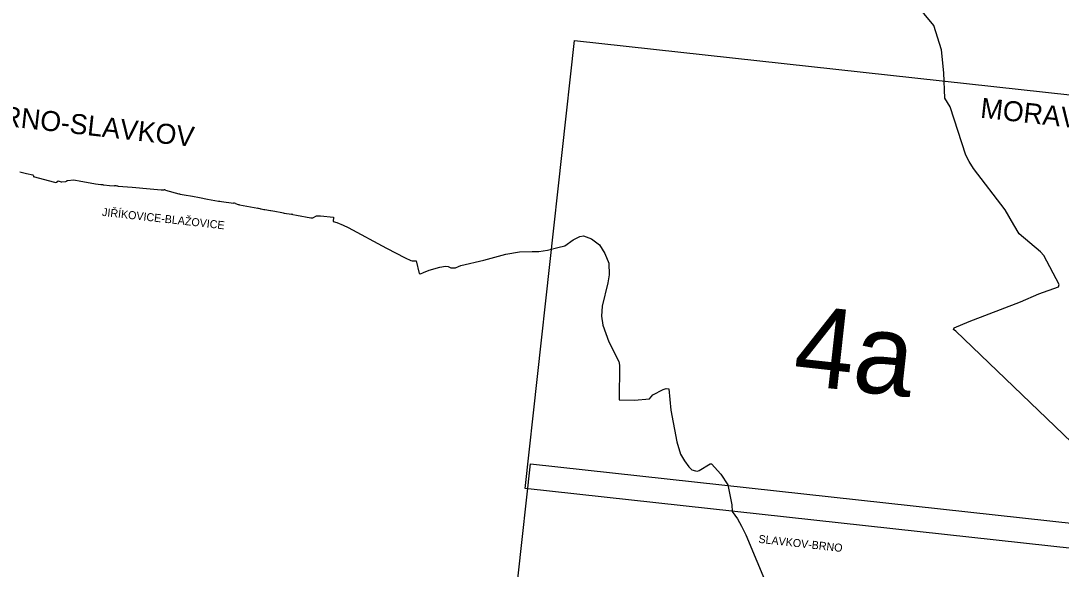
# Model space of a CAD drawing. Extents: x -678204 to -526855, y -1228851 to -1110393.
# Drawn here: x -587930 to -580130, y -1168017 to -1163908 of the extents above; entities that cross this region are included whole.
import ezdxf

# ---------------------------------------------------------------- set-up
doc = ezdxf.new("R2010")
doc.units = 0
for name, color, linetype in [('00_n_cyklo popisy detaily', 7, 'Continuous'), ('00_n_cyklo popisy ostatni', 7, 'Continuous'), ('00_n_cyklo provereni vedlejsi', 7, 'Continuous'), ('00_n_cyklo prujezdne rekreacni vedlejsi', 7, 'Continuous'), ('00_n_cyklo realizace rekreacni vedlejsi', 7, 'Continuous'), ('00_n_cyklo studie rekreacni vedlejsi', 7, 'Continuous'), ('00_n_cyklo trasovani rekreacni vedlejsi', 7, 'Continuous'), ('_HELP', 7, 'Continuous')]:
    doc.layers.add(name, color=color, linetype=linetype)

msp = doc.modelspace()

# ---------------------------------------------------------------- linework, layer by layer
at = {"layer": '00_n_cyklo provereni vedlejsi'}
for points in [[(-581001.8, -1164487.7), (-581010.3, -1164297.8), (-581026.2, -1164126.2), (-581083.9, -1163943.9), (-581156.1, -1163856.2), (-581240.3, -1163785.5), (-581281.7, -1163715.5), (-581430.8, -1163359.5), (-581479.7, -1163227.3), (-581607.1, -1162771.8), (-581858.6, -1162250.9), (-582154.7, -1161867.5), (-582292.2, -1161719.3), (-582389.3, -1161653.4), (-582541.6, -1161550.7), (-582550.7, -1161521.1), (-582545.6, -1161437.7), (-582553.9, -1161420.4), (-582652.6, -1161350.3), (-582831.3, -1161299.1)], [(-580285.4, -1165640.1), (-580444.5, -1165505.1), (-580486.1, -1165437.1), (-580549.4, -1165323.8), (-580787.3, -1165013.2), (-580820.8, -1164961.9), (-580844.2, -1164914.3), (-580962, -1164553.5), (-581001.8, -1164487.7)], [(-580919, -1166234.2), (-580938.2, -1166220.3), (-580933.4, -1166209.2), (-580819.5, -1166160.9), (-580434.6, -1166012.5), (-580297.3, -1165953.9), (-580150.3, -1165900.5), (-580144.5, -1165884.8), (-580259.7, -1165667.5), (-580285.4, -1165640.1)], [(-580919, -1166234.2), (-579989.5, -1167124.1), (-579982.8, -1167138.4), (-579949.1, -1167129.4), (-579898.3, -1167123.6), (-579497.8, -1167124.8), (-579364.8, -1167130.1), (-579317.1, -1167128), (-579260, -1167124.2), (-579233, -1167115.8)]]:
    msp.add_lwpolyline(points, dxfattribs=at)
at = {"layer": '00_n_cyklo prujezdne rekreacni vedlejsi'}
msp.add_line((-584995.4, -1165705.5), (-584965.2, -1165705.7), dxfattribs=at)
for points in [[(-585862, -1165364.7), (-585755.4, -1165384.4), (-585740.8, -1165383.1), (-585711.8, -1165369.2), (-585704.5, -1165368.5), (-585682.7, -1165368.5), (-585584.9, -1165380.2)], [(-585584.9, -1165380.2), (-585587.7, -1165410.6), (-585559.6, -1165419.1), (-585511.9, -1165438.5), (-585474.5, -1165455.5), (-585187.9, -1165610.7), (-585047.2, -1165684.9), (-585006, -1165704), (-584995.4, -1165705.5)], [(-584965.2, -1165705.7), (-584944.2, -1165802.4), (-584932, -1165803.7), (-584909.5, -1165793.6), (-584869.2, -1165776.2), (-584787.7, -1165752.9), (-584746.2, -1165746.3), (-584726.5, -1165749.1), (-584705.9, -1165758.1), (-584690.6, -1165759.6), (-584671.3, -1165758.5), (-584647.3, -1165749.4), (-584631.1, -1165741.1), (-584458.6, -1165701.6), (-584293.3, -1165656.8), (-584191.4, -1165637.9), (-584095.9, -1165637.5), (-584045.1, -1165636.5), (-583981.8, -1165626.8), (-583902.5, -1165606.7), (-583850, -1165593.2), (-583787.6, -1165548.3), (-583739.3, -1165523.6), (-583710.5, -1165518.4), (-583650.8, -1165540.6)], [(-583650.8, -1165540.6), (-583591.1, -1165586.9), (-583550.4, -1165650.2), (-583521.6, -1165724.5), (-583519.6, -1165810.9), (-583528.4, -1165872), (-583570.3, -1166045.5), (-583576.5, -1166120.3), (-583565.8, -1166187.4), (-583520.3, -1166312.4), (-583445.3, -1166461.8), (-583441.5, -1166489.3), (-583442.8, -1166747.9), (-583329, -1166750.2), (-583216.5, -1166739.8), (-583192, -1166710.3), (-583114.7, -1166670.3), (-583091.9, -1166663.7), (-583072.3, -1166666.1), (-583056.5, -1166824.3), (-583012.7, -1167062.9), (-582982.8, -1167155), (-582953.5, -1167206), (-582920.5, -1167249.8), (-582898.5, -1167272.6), (-582871.5, -1167280.4), (-582856.7, -1167282.7), (-582845.2, -1167277.6), (-582762.7, -1167227.4), (-582751.7, -1167226.8), (-582682.2, -1167306.2), (-582628.2, -1167384.4), (-582598.9, -1167534.1), (-582597.2, -1167584.1), (-582555.7, -1167639.5), (-582527.8, -1167694.1), (-582524.5, -1167700.9)], [(-582524.5, -1167700.9), (-582495.5, -1167760.7)], [(-582495.5, -1167760.7), (-582329, -1168154.9), (-582260.4, -1168332)]]:
    msp.add_lwpolyline(points, dxfattribs=at)
at = {"layer": '00_n_cyklo realizace rekreacni vedlejsi'}
for p, q in [((-587937.5, -1165038.6), (-587886.8, -1165051.5)), ((-587886.8, -1165051.5), (-587840.2, -1165062.7)), ((-587834.1, -1165070.5), (-587834, -1165076.1)), ((-587307.9, -1165137.6), (-587266, -1165141)), ((-587266, -1165141), (-587227.9, -1165144.1)), ((-587200.2, -1165146.4), (-587095.4, -1165155.4)), ((-587095.4, -1165155.4), (-586960.6, -1165167)), ((-586960.6, -1165167), (-586876.5, -1165174.3)), ((-586867.6, -1165174.5), (-586855.8, -1165174.2)), ((-586843.9, -1165175.7), (-586743.9, -1165204)), ((-586735.5, -1165205.9), (-586704.1, -1165211.2)), ((-586704.1, -1165211.2), (-586643, -1165222.7)), ((-586643, -1165222.7), (-586589.9, -1165232.6)), ((-586589.9, -1165232.6), (-586530.7, -1165243.2)), ((-586530.7, -1165243.2), (-586447.3, -1165258.2)), ((-586425.7, -1165261.7), (-586334.6, -1165274)), ((-586320.1, -1165277.4), (-586301.1, -1165283.7)), ((-586290.3, -1165286.5), (-586153.1, -1165311.8)), ((-586149.8, -1165312.4), (-586137.1, -1165315)), ((-586128.9, -1165316.5), (-586106.7, -1165320.8)), ((-586099.5, -1165322.1), (-586057.9, -1165329.7)), ((-586054.5, -1165330.3), (-586026.3, -1165335.3)), ((-586026.3, -1165335.3), (-585973.2, -1165345.3)), ((-585954.7, -1165348.6), (-585900.5, -1165357.8)), ((-585890.2, -1165359.6), (-585862, -1165364.7))]:
    msp.add_line(p, q, dxfattribs=at)
for centre, radius, start, end in [((-587842.1, -1165070.5), 8, 0.0656, 76.50535), ((-587629.5, -1170128), 5000, 85.07443, 85.39267), ((-586869.7, -1165094.6), 80, 265.08645, 271.47754), ((-586854.8, -1165214.2), 40, 74.23261, 91.47754), ((-586722.1, -1165127), 80, 254.23261, 260.35671), ((-586358.5, -1164766.2), 500, 259.76275, 262.27547), ((-586345.4, -1165353.3), 80, 71.551, 82.27547), ((-586275.8, -1165207.8), 80, 251.551, 259.54786), ((-586198.4, -1165557.7), 250, 78.78495, 79.54786), ((-585942.6, -1164334.1), 1000, 258.78495, 259.26019), ((-585920.3, -1164338.3), 1000, 259.26019, 259.67582), ((-585878.7, -1164345.9), 1000, 259.67582, 259.87464), ((-585788, -1164362.6), 1000, 259.3266, 260.40113), ((-586067.2, -1166343.8), 1000, 79.80428, 80.40113)]:
    msp.add_arc(centre, radius, start, end, dxfattribs=at)
at = {"layer": '00_n_cyklo studie rekreacni vedlejsi'}
msp.add_line((-587837.1, -1165075.5), (-587677.3, -1165117.2), dxfattribs=at)
msp.add_lwpolyline([(-587677.3, -1165117.2), (-587667.1, -1165119.3), (-587662.1, -1165117.3), (-587652.2, -1165108.2), (-587648.8, -1165106.8), (-587628, -1165114.9), (-587622, -1165115.3), (-587592.2, -1165110.8), (-587587.9, -1165108.2), (-587583, -1165104.7), (-587577.3, -1165103.5), (-587534.3, -1165100.3), (-587520.4, -1165101.2), (-587492, -1165106.6), (-587368.7, -1165130.1), (-587329.5, -1165134), (-587317.8, -1165134.8), (-587312.2, -1165136.3), (-587307.8, -1165137.1)], dxfattribs=at)
at = {"layer": '00_n_cyklo trasovani rekreacni vedlejsi'}
for p, q in [((-587937.5, -1165038.6), (-587886.8, -1165051.5)), ((-587886.8, -1165051.5), (-587840.2, -1165062.7)), ((-587837.1, -1165075.5), (-587677.3, -1165117.2)), ((-587834.1, -1165070.5), (-587834, -1165076.1)), ((-587307.9, -1165137.6), (-587266, -1165141)), ((-587266, -1165141), (-587227.9, -1165144.1)), ((-587200.2, -1165146.4), (-587095.4, -1165155.4)), ((-587095.4, -1165155.4), (-586960.6, -1165167)), ((-586960.6, -1165167), (-586876.5, -1165174.3)), ((-586867.6, -1165174.5), (-586855.8, -1165174.2)), ((-586843.9, -1165175.7), (-586743.9, -1165204)), ((-586735.5, -1165205.9), (-586704.1, -1165211.2)), ((-586704.1, -1165211.2), (-586643, -1165222.7)), ((-586643, -1165222.7), (-586589.9, -1165232.6)), ((-586589.9, -1165232.6), (-586530.7, -1165243.2)), ((-586530.7, -1165243.2), (-586447.3, -1165258.2)), ((-586425.7, -1165261.7), (-586334.6, -1165274)), ((-586320.1, -1165277.4), (-586301.1, -1165283.7)), ((-586290.3, -1165286.5), (-586153.1, -1165311.8)), ((-586149.8, -1165312.4), (-586137.1, -1165315)), ((-586128.9, -1165316.5), (-586106.7, -1165320.8)), ((-586099.5, -1165322.1), (-586057.9, -1165329.7)), ((-586054.5, -1165330.3), (-586026.3, -1165335.3)), ((-586026.3, -1165335.3), (-585973.2, -1165345.3)), ((-585954.7, -1165348.6), (-585900.5, -1165357.8)), ((-585890.2, -1165359.6), (-585862, -1165364.7)), ((-584995.4, -1165705.5), (-584965.2, -1165705.7))]:
    msp.add_line(p, q, dxfattribs=at)
for points in [[(-581001.8, -1164487.7), (-581010.3, -1164297.8), (-581026.2, -1164126.2), (-581083.9, -1163943.9), (-581156.1, -1163856.2), (-581240.3, -1163785.5), (-581281.7, -1163715.5), (-581430.8, -1163359.5), (-581479.7, -1163227.3), (-581607.1, -1162771.8), (-581858.6, -1162250.9), (-582154.7, -1161867.5), (-582292.2, -1161719.3), (-582389.3, -1161653.4), (-582541.6, -1161550.7), (-582550.7, -1161521.1), (-582545.6, -1161437.7), (-582553.9, -1161420.4), (-582652.6, -1161350.3), (-582831.3, -1161299.1)], [(-580285.4, -1165640.1), (-580444.5, -1165505.1), (-580486.1, -1165437.1), (-580549.4, -1165323.8), (-580787.3, -1165013.2), (-580820.8, -1164961.9), (-580844.2, -1164914.3), (-580962, -1164553.5), (-581001.8, -1164487.7)], [(-587677.3, -1165117.2), (-587667.1, -1165119.3), (-587662.1, -1165117.3), (-587652.2, -1165108.2), (-587648.8, -1165106.8), (-587628, -1165114.9), (-587622, -1165115.3), (-587592.2, -1165110.8), (-587587.9, -1165108.2), (-587583, -1165104.7), (-587577.3, -1165103.5), (-587534.3, -1165100.3), (-587520.4, -1165101.2), (-587492, -1165106.6), (-587368.7, -1165130.1), (-587329.5, -1165134), (-587317.8, -1165134.8), (-587312.2, -1165136.3), (-587307.8, -1165137.1)], [(-585862, -1165364.7), (-585755.4, -1165384.4), (-585740.8, -1165383.1), (-585711.8, -1165369.2), (-585704.5, -1165368.5), (-585682.7, -1165368.5), (-585584.9, -1165380.2)], [(-585584.9, -1165380.2), (-585587.7, -1165410.6), (-585559.6, -1165419.1), (-585511.9, -1165438.5), (-585474.5, -1165455.5), (-585187.9, -1165610.7), (-585047.2, -1165684.9), (-585006, -1165704), (-584995.4, -1165705.5)], [(-584965.2, -1165705.7), (-584944.2, -1165802.4), (-584932, -1165803.7), (-584909.5, -1165793.6), (-584869.2, -1165776.2), (-584787.7, -1165752.9), (-584746.2, -1165746.3), (-584726.5, -1165749.1), (-584705.9, -1165758.1), (-584690.6, -1165759.6), (-584671.3, -1165758.5), (-584647.3, -1165749.4), (-584631.1, -1165741.1), (-584458.6, -1165701.6), (-584293.3, -1165656.8), (-584191.4, -1165637.9), (-584095.9, -1165637.5), (-584045.1, -1165636.5), (-583981.8, -1165626.8), (-583902.5, -1165606.7), (-583850, -1165593.2), (-583787.6, -1165548.3), (-583739.3, -1165523.6), (-583710.5, -1165518.4), (-583650.8, -1165540.6)], [(-583650.8, -1165540.6), (-583591.1, -1165586.9), (-583550.4, -1165650.2), (-583521.6, -1165724.5), (-583519.6, -1165810.9), (-583528.4, -1165872), (-583570.3, -1166045.5), (-583576.5, -1166120.3), (-583565.8, -1166187.4), (-583520.3, -1166312.4), (-583445.3, -1166461.8), (-583441.5, -1166489.3), (-583442.8, -1166747.9), (-583329, -1166750.2), (-583216.5, -1166739.8), (-583192, -1166710.3), (-583114.7, -1166670.3), (-583091.9, -1166663.7), (-583072.3, -1166666.1), (-583056.5, -1166824.3), (-583012.7, -1167062.9), (-582982.8, -1167155), (-582953.5, -1167206), (-582920.5, -1167249.8), (-582898.5, -1167272.6), (-582871.5, -1167280.4), (-582856.7, -1167282.7), (-582845.2, -1167277.6), (-582762.7, -1167227.4), (-582751.7, -1167226.8), (-582682.2, -1167306.2), (-582628.2, -1167384.4), (-582598.9, -1167534.1), (-582597.2, -1167584.1), (-582555.7, -1167639.5), (-582527.8, -1167694.1), (-582524.5, -1167700.9)], [(-580919, -1166234.2), (-580938.2, -1166220.3), (-580933.4, -1166209.2), (-580819.5, -1166160.9), (-580434.6, -1166012.5), (-580297.3, -1165953.9), (-580150.3, -1165900.5), (-580144.5, -1165884.8), (-580259.7, -1165667.5), (-580285.4, -1165640.1)], [(-580919, -1166234.2), (-579989.5, -1167124.1), (-579982.8, -1167138.4), (-579949.1, -1167129.4), (-579898.3, -1167123.6), (-579497.8, -1167124.8), (-579364.8, -1167130.1), (-579317.1, -1167128), (-579260, -1167124.2), (-579233, -1167115.8)], [(-582524.5, -1167700.9), (-582495.5, -1167760.7)], [(-582495.5, -1167760.7), (-582329, -1168154.9), (-582260.4, -1168332)]]:
    msp.add_lwpolyline(points, dxfattribs=at)
for centre, radius, start, end in [((-587842.1, -1165070.5), 8, 0.0656, 76.50535), ((-587629.5, -1170128), 5000, 85.07443, 85.39267), ((-586869.7, -1165094.6), 80, 265.08645, 271.47754), ((-586854.8, -1165214.2), 40, 74.23261, 91.47754), ((-586722.1, -1165127), 80, 254.23261, 260.35671), ((-586358.5, -1164766.2), 500, 259.76275, 262.27547), ((-586345.4, -1165353.3), 80, 71.551, 82.27547), ((-586275.8, -1165207.8), 80, 251.551, 259.54786), ((-586198.4, -1165557.7), 250, 78.78495, 79.54786), ((-585942.6, -1164334.1), 1000, 258.78495, 259.26019), ((-585920.3, -1164338.3), 1000, 259.26019, 259.67582), ((-585878.7, -1164345.9), 1000, 259.67582, 259.87464), ((-585788, -1164362.6), 1000, 259.3266, 260.40113), ((-586067.2, -1166343.8), 1000, 79.80428, 80.40113)]:
    msp.add_arc(centre, radius, start, end, dxfattribs=at)
at = {"layer": '_HELP'}
for points in [[(-583778.8, -1164054.2), (-579064.3, -1164571.9), (-579433, -1167929.4), (-584147.5, -1167411.7)], [(-584109.1, -1167226.8), (-579394.6, -1167744.5), (-579763.3, -1171102), (-584477.8, -1170584.3)]]:
    msp.add_lwpolyline(points, close=True, dxfattribs=at)

# ---------------------------------------------------------------- texts
at = {"layer": '00_n_cyklo popisy detaily'}
for s, p in [('JIŘÍKOVICE-BLAŽOVICE', (-587322.9, -1165369)), ('JIŘÍKOVICE-BLAŽOVICE', (-587322.9, -1165369)), ('JIŘÍKOVICE-BLAŽOVICE', (-587322.9, -1165369)), ('SLAVKOV-BRNO', (-582402, -1167819))]:
    msp.add_text(s, height=60, rotation=353.68355, dxfattribs=at).set_placement(p)
at = {"layer": '00_n_cyklo popisy ostatni'}
for s, p in [('BRNO-SLAVKOV', (-588211.6, -1164678.3)), ('MORAVSKÝ KRAS-SLAVKOV', (-580740.5, -1164632.9))]:
    msp.add_text(s, height=150, rotation=353.68355, dxfattribs=at).set_placement(p)
at = {"layer": '_HELP'}
msp.add_text('4a', height=600, rotation=353.68355, dxfattribs=at).set_placement((-582152.7, -1166630.1))

doc.saveas('drawing.dxf')
